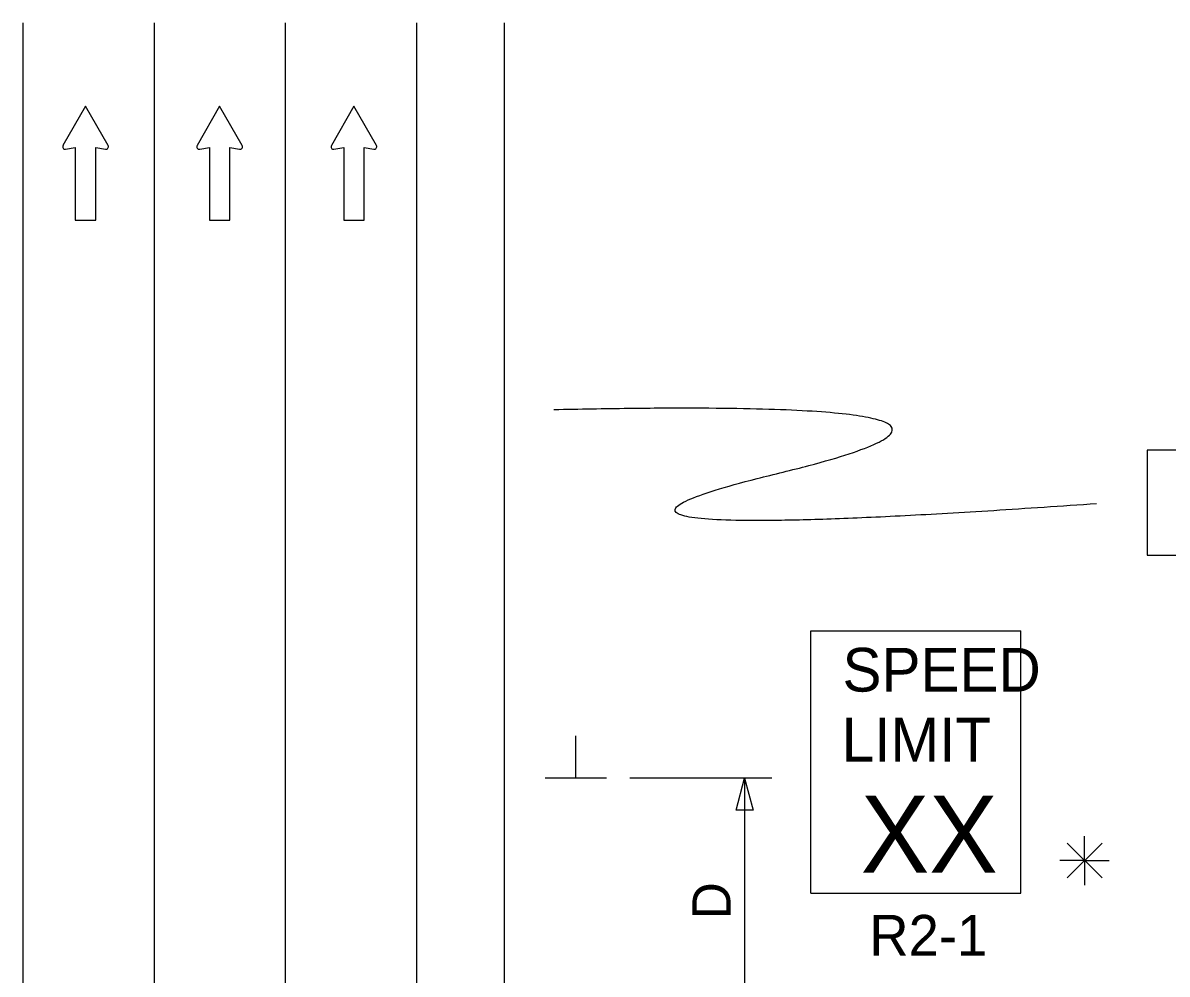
# Model space of a CAD drawing. Extents: x 16727 to 18475, y 5729 to 6909.
# Drawn here: x 16917.2 to 17126.5, y 6717.1 to 6891.2 of the extents above; entities that cross this region are included whole.
import ezdxf

# ---------------------------------------------------------------- set-up
doc = ezdxf.new("R2010")
doc.units = 0
for name, color, linetype in [('ALI_LEGAL_EX', 7, 'Continuous'), ('MT_SCRATCH_LEVEL_E', 7, 'Continuous'), ('PAVT_EDGE_EX', 7, 'Continuous'), ('TRAFFIC_SIGNS_PR', 7, 'Continuous'), ('TYPICAL_TEXT_DIMEN_PR', 7, 'Continuous')]:
    doc.layers.add(name, color=color, linetype=linetype)

msp = doc.modelspace()

# ---------------------------------------------------------------- linework, layer by layer
at = {"layer": 'ALI_LEGAL_EX'}
for p, q in [((16941.23, 6891.16), (16941.23, 6061.98)), ((16965.23, 6891.16), (16965.23, 6061.98)), ((16965.23, 6891.16), (16965.23, 6061.98))]:
    msp.add_line(p, q, dxfattribs=at)
for points in [[(16941.23, 6891.16), (16941.23, 6866.16)], [(16965.23, 6891.16), (16965.23, 6866.16)], [(16941.23, 6791.16), (16941.23, 6766.16)], [(16965.23, 6791.16), (16965.23, 6766.16)]]:
    msp.add_lwpolyline(points, dxfattribs=at)
at = {"layer": 'MT_SCRATCH_LEVEL_E'}
for p, q in [((16928.67, 6875.95), (16924.56, 6868.71)), ((16928.67, 6875.95), (16924.56, 6868.71)), ((16932.82, 6868.71), (16928.67, 6875.95)), ((16932.82, 6868.71), (16928.67, 6875.95)), ((16953.2, 6875.95), (16949.09, 6868.71)), ((16953.2, 6875.95), (16949.09, 6868.71)), ((16957.35, 6868.71), (16953.2, 6875.95)), ((16957.35, 6868.71), (16953.2, 6875.95)), ((16977.76, 6875.95), (16973.65, 6868.71)), ((16977.76, 6875.95), (16973.65, 6868.71)), ((16981.9, 6868.71), (16977.76, 6875.95)), ((16981.9, 6868.71), (16977.76, 6875.95)), ((16925.04, 6868.03), (16926.82, 6868.34)), ((16925.04, 6868.03), (16926.82, 6868.34)), ((16926.82, 6868.34), (16926.82, 6855.09)), ((16926.82, 6868.34), (16926.82, 6855.09)), ((16930.56, 6855.09), (16930.56, 6868.34)), ((16930.56, 6868.34), (16932.34, 6868.03)), ((16930.56, 6855.09), (16930.56, 6868.34)), ((16930.56, 6868.34), (16932.34, 6868.03)), ((16949.57, 6868.03), (16951.35, 6868.34)), ((16949.57, 6868.03), (16951.35, 6868.34)), ((16951.35, 6868.34), (16951.35, 6855.09)), ((16951.35, 6868.34), (16951.35, 6855.09)), ((16955.09, 6855.09), (16955.09, 6868.34)), ((16955.09, 6868.34), (16956.87, 6868.03)), ((16955.09, 6855.09), (16955.09, 6868.34)), ((16955.09, 6868.34), (16956.87, 6868.03)), ((16974.13, 6868.03), (16975.9, 6868.34)), ((16974.13, 6868.03), (16975.9, 6868.34)), ((16975.9, 6868.34), (16975.9, 6855.09)), ((16975.9, 6868.34), (16975.9, 6855.09)), ((16979.65, 6855.09), (16979.65, 6868.34)), ((16979.65, 6868.34), (16981.42, 6868.03)), ((16979.65, 6855.09), (16979.65, 6868.34)), ((16979.65, 6868.34), (16981.42, 6868.03)), ((16926.82, 6855.09), (16930.56, 6855.09)), ((16926.82, 6855.09), (16930.56, 6855.09)), ((16951.35, 6855.09), (16955.09, 6855.09)), ((16951.35, 6855.09), (16955.09, 6855.09)), ((16975.9, 6855.09), (16979.65, 6855.09)), ((16975.9, 6855.09), (16979.65, 6855.09))]:
    msp.add_line(p, q, dxfattribs=at)
for centre, start, end in [((16924.97, 6868.49), 150.4248, 279.9638), ((16924.97, 6868.49), 150.4248, 279.9638), ((16932.41, 6868.49), 260.0362, 29.7731), ((16932.41, 6868.49), 260.0362, 29.7731), ((16949.49, 6868.49), 150.4248, 279.9638), ((16949.49, 6868.49), 150.4248, 279.9638), ((16956.94, 6868.49), 260.0362, 29.7731), ((16956.94, 6868.49), 260.0362, 29.7731), ((16974.05, 6868.49), 150.4248, 279.9638), ((16974.05, 6868.49), 150.4248, 279.9638), ((16981.49, 6868.49), 260.0362, 29.7731), ((16981.49, 6868.49), 260.0362, 29.7731)]:
    msp.add_arc(centre, 0.463, start, end, dxfattribs=at)
at = {"layer": 'PAVT_EDGE_EX'}
for p, q in [((16917.23, 6891.16), (16917.23, 6061.98)), ((16917.23, 6891.16), (16917.23, 6061.98)), ((16989.23, 6891.16), (16989.23, 6061.98)), ((17005.23, 6891.16), (17005.23, 6061.98))]:
    msp.add_line(p, q, dxfattribs=at)
at = {"layer": 'TRAFFIC_SIGNS_PR'}
for p, q in [((17061.37, 6779.97), (17099.77, 6779.97)), ((17061.37, 6731.97), (17061.37, 6779.97)), ((17099.77, 6731.97), (17099.77, 6779.97)), ((17061.37, 6731.97), (17099.77, 6731.97))]:
    msp.add_line(p, q, dxfattribs=at)
msp.add_lwpolyline([(17122.83, 6793.8), (17161.23, 6793.8), (17161.23, 6812.99), (17122.83, 6812.99)], close=True, dxfattribs=at)
msp.add_open_spline([(17113.61, 6803.19), (16998.38, 6794.96), (17112.29, 6822.54), (17014.35, 6820.37)], degree=2, dxfattribs=at)
at = {"layer": 'TYPICAL_TEXT_DIMEN_PR'}
for p, q in [((17018.35, 6752.97), (17018.35, 6760.76)), ((17023.98, 6752.97), (17012.73, 6752.97)), ((17054.23, 6752.97), (17028.23, 6752.97)), ((17047.66, 6747.11), (17049.23, 6752.97)), ((17049.23, 6752.97), (17049.23, 6702.97)), ((17049.23, 6752.97), (17050.8, 6747.11)), ((17049.23, 6747.11), (17047.66, 6747.11)), ((17050.8, 6747.11), (17049.23, 6747.11)), ((17108.22, 6741.1), (17114.6, 6734.73)), ((17114.6, 6741.1), (17108.22, 6734.73)), ((17111.41, 6737.91), (17111.41, 6742.37)), ((17111.41, 6737.91), (17106.88, 6737.91)), ((17111.41, 6737.91), (17114.6, 6737.91)), ((17111.41, 6737.91), (17115.89, 6737.91)), ((17111.41, 6737.91), (17111.41, 6733.41))]:
    msp.add_line(p, q, dxfattribs=at)

# ---------------------------------------------------------------- texts
at = {"layer": 'TRAFFIC_SIGNS_PR'}
for s, height, p in [('SPEED', 8, (17067.13, 6768.83)), ('LIMIT', 8, (17066.97, 6756.03)), ('XX', 14.031, (17070.48, 6735.73)), ('R2-1', 7.44, (17072.04, 6720.53))]:
    msp.add_text(s, height=height, dxfattribs=at).set_placement(p)
at = {"layer": 'TYPICAL_TEXT_DIMEN_PR'}
msp.add_text('D', height=7, rotation=90, dxfattribs=at).set_placement((17046.67, 6727.19))

doc.saveas('drawing.dxf')
